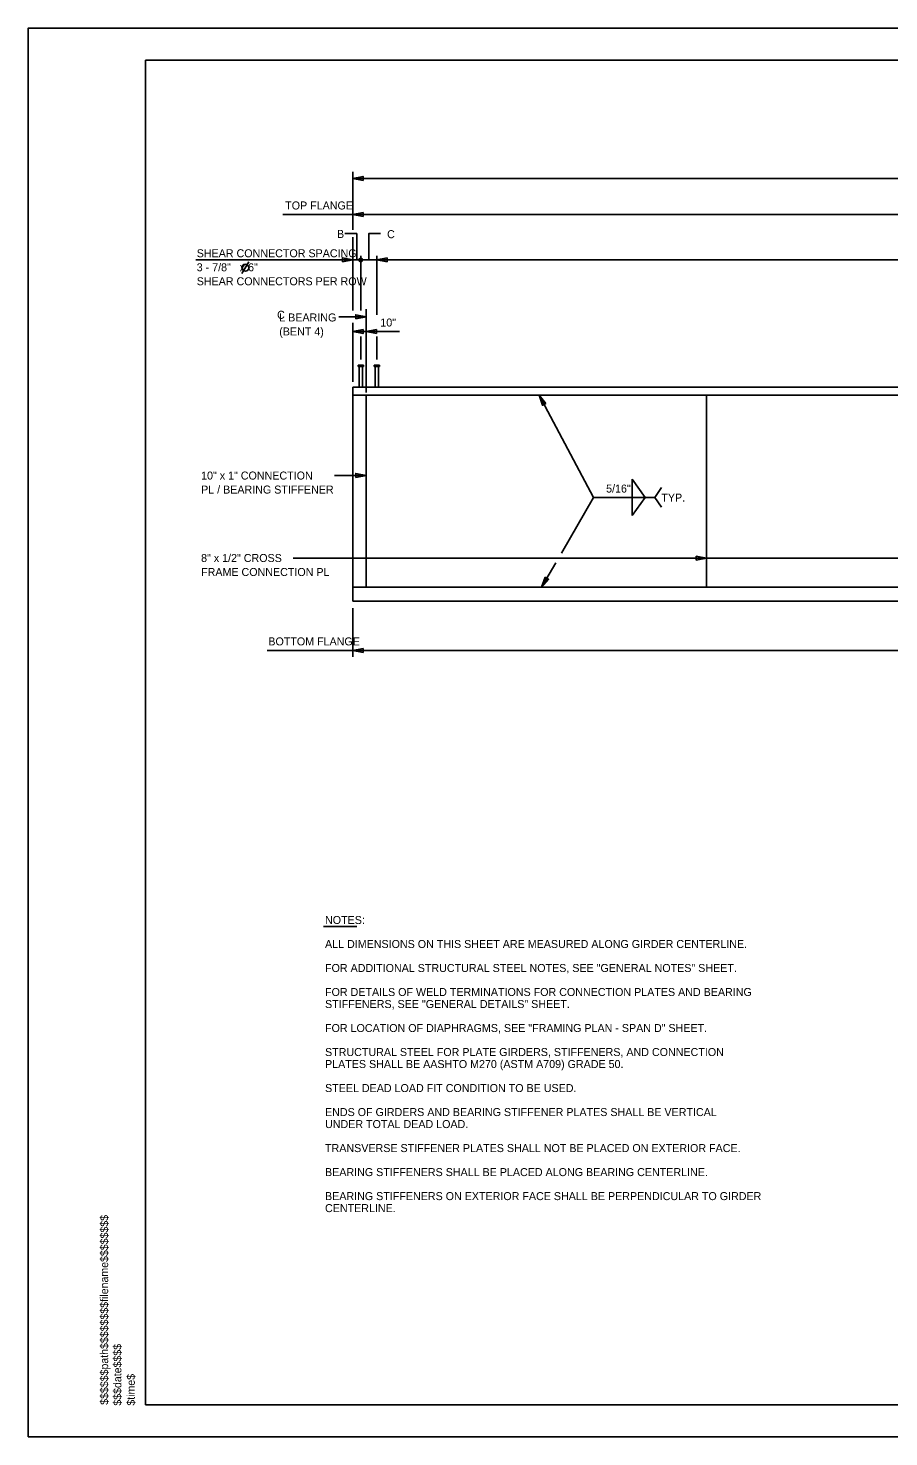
# Model space of a CAD drawing. Extents: x -305 to -161, y -187 to -99.
# Drawn here: x -305.2 to -251.4, y -187.5 to -99.5 of the extents above; entities that cross this region are included whole.
import ezdxf

# ---------------------------------------------------------------- set-up
doc = ezdxf.new("R2010")
doc.units = 0
for name, color, linetype in [('BR_AUTO DIMENSION', 7, 'Continuous'), ('BR_BORDER LINES', 7, 'Continuous'), ('BR_CENTER LINES', 7, 'Continuous'), ('BR_STRUCTURAL STEEL', 7, 'Continuous'), ('BR_TEXT', 7, 'Continuous'), ('Default', 7, 'Continuous'), ('Level 31', 7, 'Continuous'), ('RD_SHT_ID', 7, 'Continuous')]:
    doc.layers.add(name, color=color, linetype=linetype)

msp = doc.modelspace()

# ---------------------------------------------------------------- linework, layer by layer
at = {"layer": 'BR_AUTO DIMENSION'}
for p, q in [((-284.888, -112.097), (-284.888, -108.463)), ((-284.888, -108.876), (-176.804, -108.876)), ((-284.888, -111.134), (-289.258, -111.134)), ((-284.888, -111.134), (-176.804, -111.134)), ((-284.888, -117.118), (-284.888, -112.544)), ((-284.888, -113.971), (-294.705, -113.971)), ((-283.388, -113.971), (-284.888, -113.971)), ((-284.388, -117.118), (-284.388, -113.71)), ((-283.388, -117.407), (-283.388, -113.71)), ((-178.304, -113.971), (-283.388, -113.971)), ((-284.055, -117.522), (-285.757, -117.522)), ((-284.888, -121.593), (-284.888, -117.889)), ((-284.888, -118.446), (-281.974, -118.446)), ((-284.388, -120.185), (-284.388, -118.756)), ((-283.388, -120.185), (-283.388, -118.756)), ((-269.841, -128.801), (-273.229, -122.412)), ((-284.055, -127.431), (-286.02, -127.431)), ((-267.425, -127.667), (-267.425, -129.935)), ((-267.425, -127.667), (-266.619, -128.801)), ((-266.016, -128.801), (-265.583, -128.194)), ((-269.841, -128.801), (-271.851, -132.282)), ((-269.841, -128.801), (-266.016, -128.801)), ((-267.425, -129.935), (-266.619, -128.801)), ((-266.016, -128.801), (-265.583, -129.408)), ((-198.921, -132.601), (-288.61, -132.601)), ((-272.203, -132.892), (-273.082, -134.412)), ((-284.888, -135.715), (-284.888, -138.768)), ((-284.888, -138.367), (-290.236, -138.367)), ((-284.888, -138.367), (-176.804, -138.367)), ((-286.712, -155.612), (-284.636, -155.612))]:
    msp.add_line(p, q, dxfattribs=at)
for points in [[(-284.238, -109.001), (-284.888, -108.876), (-284.238, -108.751)], [(-284.238, -111.259), (-284.888, -111.134), (-284.238, -111.009)], [(-285.538, -114.096), (-284.888, -113.971), (-285.538, -113.846)], [(-282.738, -114.096), (-283.388, -113.971), (-282.738, -113.846)], [(-284.705, -117.647), (-284.055, -117.522), (-284.705, -117.397)], [(-284.238, -118.321), (-284.888, -118.446), (-284.238, -118.571)], [(-283.405, -118.571), (-284.055, -118.446), (-283.405, -118.321)], [(-272.814, -122.928), (-273.229, -122.412), (-273.035, -123.045)], [(-284.705, -127.556), (-284.055, -127.431), (-284.705, -127.306)], [(-263.421, -132.726), (-262.771, -132.601), (-263.421, -132.476)], [(-272.865, -133.787), (-273.082, -134.412), (-272.648, -133.912)], [(-284.238, -138.492), (-284.888, -138.367), (-284.238, -138.242)]]:
    msp.add_lwpolyline(points, close=True, dxfattribs=at)
for points in [[(-284.638, -113.971), (-284.638, -112.325), (-285.378, -112.325)], [(-283.888, -113.971), (-283.888, -112.325), (-283.148, -112.325)]]:
    msp.add_lwpolyline(points, dxfattribs=at)
msp.add_circle((-284.388, -113.971), 0.111, dxfattribs=at)
at = {"layer": 'BR_BORDER LINES'}
for p, q in [((-163.178, -101.489), (-297.843, -101.489)), ((-297.843, -185.489), (-297.843, -101.489)), ((-297.843, -185.489), (-163.178, -185.489))]:
    msp.add_line(p, q, dxfattribs=at)
at = {"layer": 'BR_CENTER LINES'}
msp.add_line((-284.055, -117.035), (-284.055, -122.256), dxfattribs=at)
at = {"layer": 'BR_STRUCTURAL STEEL'}
for p, q in [((-284.888, -121.912), (-176.804, -121.912)), ((-284.888, -121.912), (-284.888, -122.412)), ((-284.888, -122.412), (-176.804, -122.412)), ((-284.888, -122.412), (-284.888, -134.412)), ((-284.055, -122.412), (-284.055, -134.412)), ((-262.771, -122.412), (-262.771, -134.412)), ((-284.888, -134.412), (-176.804, -134.412)), ((-284.888, -134.412), (-284.888, -135.287)), ((-284.888, -135.287), (-176.804, -135.287))]:
    msp.add_line(p, q, dxfattribs=at)
at = {"layer": 'BR_TEXT'}
msp.add_line((-291.812, -114.817), (-291.392, -114.089), dxfattribs=at)
msp.add_circle((-291.602, -114.453), 0.22, dxfattribs=at)
at = {"layer": 'Default'}
for p, q in [((-284.56, -120.537), (-284.56, -120.631)), ((-284.56, -120.537), (-284.216, -120.537)), ((-284.216, -120.537), (-284.216, -120.631)), ((-283.56, -120.537), (-283.56, -120.631)), ((-283.56, -120.537), (-283.216, -120.537)), ((-283.216, -120.537), (-283.216, -120.631)), ((-284.56, -120.631), (-284.216, -120.631)), ((-284.497, -120.631), (-284.497, -121.912)), ((-284.279, -120.631), (-284.279, -121.912)), ((-283.56, -120.631), (-283.216, -120.631)), ((-283.497, -120.631), (-283.497, -121.912)), ((-283.279, -120.631), (-283.279, -121.912))]:
    msp.add_line(p, q, dxfattribs=at)
at = {"layer": 'Level 31'}
msp.add_lwpolyline([(-305.176, -187.489), (-161.176, -187.489), (-161.176, -99.489), (-305.176, -99.489)], close=True, dxfattribs=at)

# ---------------------------------------------------------------- texts
at = {"layer": 'BR_AUTO DIMENSION'}
for s, p in [('TOP FLANGE', (-289.11, -110.815)), ('B', (-285.874, -112.593)), ('C', (-282.741, -112.609)), ('10"', (-283.164, -118.127)), ('5/16"', (-269.053, -128.501)), ('TYP.', (-265.599, -129.067)), ('BOTTOM FLANGE', (-290.164, -138.048)), ('NOTES:', (-286.621, -155.451)), ('ALL DIMENSIONS ON THIS SHEET ARE MEASURED ALONG GIRDER CENTERLINE.', (-286.621, -156.951)), ('FOR ADDITIONAL STRUCTURAL STEEL NOTES, SEE "GENERAL NOTES" SHEET.', (-286.621, -158.451)), ('FOR DETAILS OF WELD TERMINATIONS FOR CONNECTION PLATES AND BEARING ', (-286.621, -159.951)), ('STIFFENERS, SEE "GENERAL DETAILS" SHEET.', (-286.621, -160.701)), ('FOR LOCATION OF DIAPHRAGMS, SEE "FRAMING PLAN - SPAN D" SHEET.', (-286.621, -162.201)), ('STRUCTURAL STEEL FOR PLATE GIRDERS, STIFFENERS, AND CONNECTION ', (-286.621, -163.701)), ('PLATES SHALL BE AASHTO M270 (ASTM A709) GRADE 50.', (-286.621, -164.451)), ('STEEL DEAD LOAD FIT CONDITION TO BE USED.', (-286.621, -165.951)), ('ENDS OF GIRDERS AND BEARING STIFFENER PLATES SHALL BE VERTICAL', (-286.621, -167.451)), ('UNDER TOTAL DEAD LOAD.', (-286.621, -168.201)), ('TRANSVERSE STIFFENER PLATES SHALL NOT BE PLACED ON EXTERIOR FACE.', (-286.621, -169.701)), ('BEARING STIFFENERS SHALL BE PLACED ALONG BEARING CENTERLINE.', (-286.621, -171.201)), ('BEARING STIFFENERS ON EXTERIOR FACE SHALL BE PERPENDICULAR TO GIRDER', (-286.621, -172.701)), ('CENTERLINE.', (-286.621, -173.451))]:
    msp.add_text(s, height=0.5, rotation=360, dxfattribs=at).set_placement(p)
at = {"layer": 'BR_TEXT'}
for s, p in [('SHEAR CONNECTOR SPACING', (-294.641, -113.801)), ('3 - 7/8"   x 6" ', (-294.641, -114.676)), ('SHEAR CONNECTORS PER ROW', (-294.641, -115.551)), ('C', (-289.618, -117.645)), ('L BEARING', (-289.483, -117.811)), ('(BENT 4)', (-289.483, -118.686)), ('10" x 1" CONNECTION ', (-294.367, -127.688)), ('PL / BEARING STIFFENER', (-294.367, -128.563)), ('8" x 1/2" CROSS ', (-294.367, -132.838)), ('FRAME CONNECTION PL', (-294.367, -133.713))]:
    msp.add_text(s, height=0.5, rotation=360, dxfattribs=at).set_placement(p)
at = {"layer": 'RD_SHT_ID'}
for s, height, p in [('$$$$$$path$$$$$$$$filename$$$$$$$$', 0.49387, (-300.176, -185.489)), ('$$$date$$$$', 0.49387, (-299.353, -185.542)), ('$time$', 0.4939, (-298.509, -185.542))]:
    msp.add_text(s, height=height, rotation=90, dxfattribs=at).set_placement(p)

doc.saveas('drawing.dxf')
